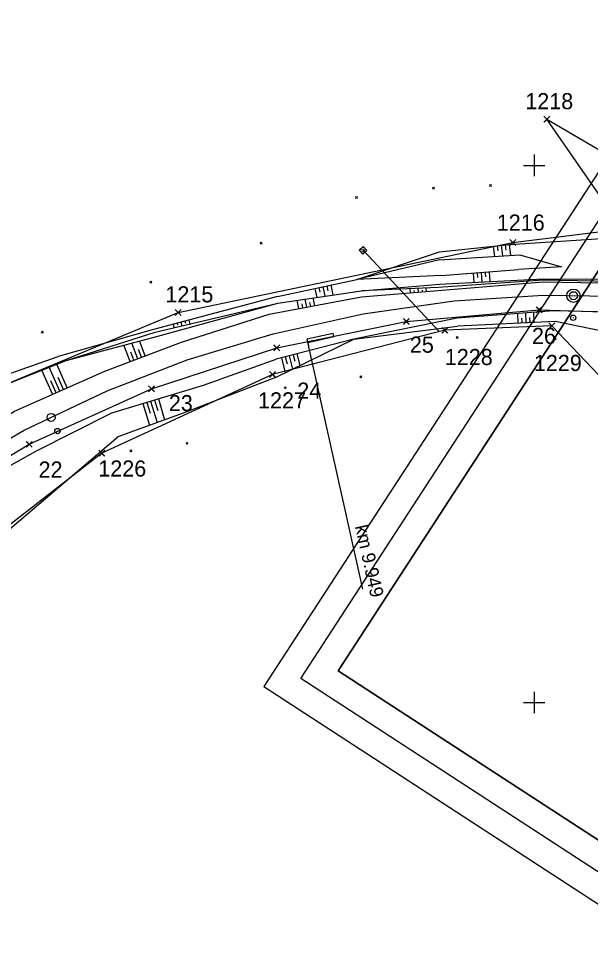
# Model space of a CAD drawing. Extents: x -866402 to -860377, y -1041908 to -1038598.
# Drawn here: x -862396.1 to -862289.5, y -1039343.6 to -1039172.6 of the extents above; entities that cross this region are included whole.
import ezdxf

# ---------------------------------------------------------------- set-up
doc = ezdxf.new("R2010")
doc.units = 0
for name, color, linetype in [('PS 01 trasa', 7, 'Continuous'), ('PS 02 trasa', 7, 'Continuous'), ('SO 01 trasa', 7, 'Continuous'), ('SZDC', 7, 'Continuous'), ('Vrstva 1', 7, 'Continuous'), ('Vrstva 25', 7, 'Continuous'), ('Vrstva 36', 7, 'Continuous'), ('Vrstva 48', 7, 'Continuous'), ('Vrstva 49', 7, 'Continuous'), ('Vrstva 5', 7, 'Continuous'), ('Vrstva 60', 7, 'Continuous'), ('Vrstva 7', 7, 'Continuous'), ('Vrstva 9', 7, 'Continuous')]:
    doc.layers.add(name, color=color, linetype=linetype)

msp = doc.modelspace()

# ---------------------------------------------------------------- linework, layer by layer
at = {"layer": 'PS 01 trasa'}
for points in [[(-862394.03, -1039251.93), (-862371.24, -1039241.59), (-862347.95, -1039233.96), (-862323.82, -1039229.06), (-862299.09, -1039226.88)], [(-862299.09, -1039226.88), (-862273.29, -1039227.68), (-862248.85, -1039231.2), (-862224.66, -1039236.92), (-862200.64, -1039243.69), (-862176.76, -1039250.51), (-862152.59, -1039257.52), (-862128.57, -1039264.44), (-862103.22, -1039271.85), (-862102.22, -1039272.14), (-862096.54, -1039273.77), (-862095.01, -1039274.21), (-862087.95, -1039276.24), (-862082.39, -1039277.83)], [(-862500.95, -1039382.24), (-862490.8, -1039355.08), (-862481.41, -1039336.58), (-862468.07, -1039315.92), (-862454.02, -1039298.95), (-862434.76, -1039279.82), (-862415.25, -1039264.75), (-862394.03, -1039251.93)]]:
    msp.add_lwpolyline(points, dxfattribs=at)
at = {"layer": 'PS 02 trasa'}
msp.add_lwpolyline([(-862490.8, -1039355.08), (-862481.41, -1039336.58), (-862468.07, -1039315.92), (-862454.02, -1039298.95), (-862434.76, -1039279.82), (-862415.25, -1039264.75), (-862394.03, -1039251.93), (-862371.24, -1039241.59), (-862347.95, -1039233.96), (-862323.82, -1039229.06), (-862299.09, -1039226.88), (-862273.29, -1039227.68), (-862248.85, -1039231.2), (-862224.66, -1039236.92), (-862200.64, -1039243.69)], dxfattribs=at)
at = {"layer": 'SO 01 trasa'}
for points in [[(-862394.03, -1039251.93), (-862371.24, -1039241.59), (-862347.95, -1039233.96), (-862323.82, -1039229.06), (-862299.09, -1039226.88)], [(-862299.09, -1039226.88), (-862273.29, -1039227.68), (-862248.85, -1039231.2), (-862224.66, -1039236.92), (-862200.64, -1039243.69), (-862176.76, -1039250.51), (-862152.59, -1039257.52), (-862128.57, -1039264.44), (-862103.22, -1039271.85)], [(-862500.95, -1039382.24), (-862490.8, -1039355.08), (-862481.41, -1039336.58), (-862468.07, -1039315.92), (-862454.02, -1039298.95), (-862434.76, -1039279.82), (-862415.25, -1039264.75), (-862394.03, -1039251.93)]]:
    msp.add_lwpolyline(points, dxfattribs=at)
at = {"layer": 'SZDC'}
for points in [[(-862521.71, -1039358.08), (-862507.17, -1039329.53), (-862500.14, -1039305.05), (-862498.55, -1039302.13), (-862487.25, -1039304.3), (-862484.62, -1039297.79), (-862467.38, -1039281.45), (-862436.33, -1039256.55), (-862366.3, -1039227.38), (-862303.99, -1039214.35), (-862283.48, -1039211.79), (-862297.66, -1039191.42), (-862263.73, -1039211.26), (-862253.31, -1039214.94), (-862234.51, -1039218.03), (-862199.37, -1039224.74)], [(-862296.71, -1039229.87), (-862316.65, -1039230.71), (-862348.72, -1039238.93), (-862380.51, -1039253.6), (-862410.85, -1039277.18), (-862440.53, -1039308.72), (-862448.04, -1039316.67), (-862455.09, -1039324.01), (-862466.78, -1039329.47), (-862479.41, -1039335.38), (-862482.88, -1039349.12), (-862498.59, -1039394.48), (-862504.52, -1039414.78), (-862507.77, -1039442.09), (-862507.54, -1039446.34), (-862506.21, -1039471.12), (-862505.87, -1039481.53), (-862505.25, -1039500.36), (-862503.67, -1039530.11), (-862504.26, -1039560.51), (-862512.94, -1039597.44), (-862522.21, -1039619.87), (-862533.82, -1039639.47), (-862574.41, -1039691.56)], [(-862268.74, -1039234), (-862264.19, -1039247.49), (-862269.23, -1039257.19), (-862284.23, -1039242.97), (-862296.71, -1039229.87)]]:
    msp.add_lwpolyline(points, dxfattribs=at)
at = {"layer": 'Vrstva 1'}
for points in [[(-862350.36, -1039297.02), (-861294.1, -1039983.97), (-861132.18, -1039735), (-862188.44, -1039048.05)], [(-862186.98, -1039054.97), (-861139.1, -1039736.46), (-861295.57, -1039977.05), (-862343.44, -1039295.55)], [(-862336.53, -1039294.09), (-861468.88, -1039858.37), (-861317.86, -1039626.16), (-862185.51, -1039061.88)], [(-862185.51, -1039061.88), (-861317.86, -1039626.16), (-861468.88, -1039858.37), (-862336.53, -1039294.09)]]:
    msp.add_lwpolyline(points, close=True, dxfattribs=at)
msp.add_lwpolyline([(-862494.61, -1039356.98), (-862487.83, -1039342.57), (-862479.6, -1039328.11), (-862470.61, -1039314.75), (-862460.78, -1039302.18), (-862456.07, -1039296.77), (-862449.22, -1039289.53), (-862437.48, -1039278.49), (-862424.62, -1039268.05), (-862410.54, -1039258.33), (-862394.98, -1039249.32), (-862379.54, -1039241.95), (-862364.62, -1039236.19), (-862348.59, -1039231.34), (-862331.87, -1039227.62), (-862314.89, -1039225.23), (-862298.26, -1039224.19), (-862281.07, -1039224.42), (-862264.02, -1039225.97), (-862246.91, -1039228.79), (-862230.83, -1039232.57), (-862214.22, -1039237.15), (-862198.47, -1039241.66)], dxfattribs=at)
at = {"layer": 'Vrstva 25'}
msp.add_line((-862317.68, -1039230.95), (-862331.88, -1039215.82), dxfattribs=at)
at = {"layer": 'Vrstva 36'}
for p, q in [((-862331.64, -1039215.35), (-862332.09, -1039215.33)), ((-862331.25, -1039215.76), (-862332.5, -1039215.72)), ((-862331.5, -1039216.15), (-862332.28, -1039216.13))]:
    msp.add_line(p, q, dxfattribs=at)
msp.add_lwpolyline([(-862331.9, -1039216.53), (-862332.58, -1039215.8), (-862331.86, -1039215.11), (-862331.17, -1039215.84), (-862331.9, -1039216.53)], dxfattribs=at)
at = {"layer": 'Vrstva 48'}
for p, q in [((-862307.63, -1039215.04), (-862307.42, -1039216.96)), ((-862306.88, -1039214.96), (-862306.78, -1039215.94)), ((-862306.14, -1039214.88), (-862305.93, -1039216.87)), ((-862305.39, -1039214.8), (-862305.28, -1039215.81)), ((-862304.65, -1039214.72), (-862304.43, -1039216.78)), ((-862311.37, -1039220.05), (-862311.24, -1039221.8)), ((-862310.63, -1039220), (-862310.56, -1039220.88)), ((-862309.88, -1039219.94), (-862309.74, -1039221.72)), ((-862309.13, -1039219.88), (-862309.06, -1039220.78)), ((-862308.38, -1039219.82), (-862308.24, -1039221.64)), ((-862338.64, -1039222.42), (-862338.44, -1039223.34)), ((-862337.9, -1039222.27), (-862337.5, -1039224.14)), ((-862340.84, -1039222.9), (-862340.48, -1039224.58)), ((-862340.1, -1039222.74), (-862339.92, -1039223.61)), ((-862339.37, -1039222.58), (-862338.99, -1039224.36)), ((-862323.04, -1039223.74), (-862323.1, -1039222.97)), ((-862322.3, -1039223.68), (-862322.33, -1039223.31)), ((-862321.55, -1039223.61), (-862321.6, -1039222.91)), ((-862320.8, -1039223.55), (-862320.83, -1039223.22)), ((-862320.05, -1039223.49), (-862320.1, -1039222.85)), ((-862343.83, -1039226.66), (-862344.12, -1039225.12)), ((-862343.1, -1039226.52), (-862343.24, -1039225.77)), ((-862342.36, -1039226.39), (-862342.64, -1039224.9)), ((-862341.62, -1039226.25), (-862341.76, -1039225.52)), ((-862340.88, -1039226.11), (-862341.15, -1039224.68)), ((-862302.99, -1039229.37), (-862303.08, -1039227.59)), ((-862301.49, -1039229.3), (-862301.58, -1039227.48)), ((-862299.99, -1039229.22), (-862300.08, -1039227.36)), ((-862365.79, -1039229.19), (-862365.6, -1039229.9)), ((-862365.07, -1039228.99), (-862364.97, -1039229.36)), ((-862364.34, -1039228.8), (-862364.14, -1039229.55)), ((-862302.24, -1039229.33), (-862302.29, -1039228.44)), ((-862300.74, -1039229.26), (-862300.79, -1039228.34)), ((-862367.24, -1039229.57), (-862367.06, -1039230.24)), ((-862366.52, -1039229.38), (-862366.43, -1039229.73)), ((-862372.44, -1039235.47), (-862373.48, -1039232.69)), ((-862375.24, -1039236.53), (-862376.4, -1039233.47)), ((-862373.84, -1039236), (-862374.94, -1039233.08)), ((-862373.14, -1039235.73), (-862373.68, -1039234.31)), ((-862374.54, -1039236.26), (-862375.11, -1039234.77)), ((-862347.09, -1039235.82), (-862346.38, -1039238.61)), ((-862346.36, -1039235.63), (-862346.03, -1039236.95)), ((-862345.64, -1039235.45), (-862345, -1039237.94)), ((-862344.91, -1039235.26), (-862344.61, -1039236.43)), ((-862344.18, -1039235.07), (-862343.62, -1039237.26)), ((-862388.34, -1039242.01), (-862390.3, -1039237.59)), ((-862386.97, -1039241.4), (-862388.9, -1039237.04)), ((-862389.71, -1039242.62), (-862391.69, -1039238.14)), ((-862387.65, -1039241.71), (-862388.62, -1039239.51)), ((-862389.02, -1039242.32), (-862390.01, -1039240.09)), ((-862372.86, -1039244.33), (-862371.64, -1039248.4)), ((-862372.14, -1039244.12), (-862371.54, -1039246.13)), ((-862371.43, -1039243.9), (-862370.23, -1039247.88)), ((-862370.71, -1039243.69), (-862370.11, -1039245.66)), ((-862369.99, -1039243.47), (-862368.82, -1039247.37))]:
    msp.add_line(p, q, dxfattribs=at)
at = {"layer": 'Vrstva 49'}
for p, q in [((-862308.31, -1039203.58), (-862307.95, -1039203.93)), ((-862308.31, -1039203.93), (-862307.95, -1039203.58)), ((-862318.92, -1039204.06), (-862318.57, -1039204.42)), ((-862318.92, -1039204.42), (-862318.57, -1039204.06)), ((-862333.26, -1039205.82), (-862332.9, -1039206.18)), ((-862333.26, -1039206.18), (-862332.9, -1039205.82)), ((-862304.63, -1039214.72), (-862261.74, -1039211.91)), ((-862351.01, -1039214.33), (-862350.66, -1039214.68)), ((-862351.01, -1039214.68), (-862350.66, -1039214.33)), ((-862317.64, -1039216.12), (-862304.63, -1039214.72)), ((-862333.02, -1039221.22), (-862317.64, -1039216.12)), ((-862317.63, -1039217.58), (-862302.71, -1039216.67)), ((-862302.71, -1039216.67), (-862294.91, -1039218.91)), ((-862317.63, -1039217.58), (-862333.02, -1039221.22)), ((-862294.91, -1039218.91), (-862302.9, -1039219.41)), ((-862317.35, -1039220.51), (-862333.02, -1039221.22)), ((-862317.35, -1039220.51), (-862302.9, -1039219.41)), ((-862371.57, -1039221.58), (-862371.22, -1039221.94)), ((-862371.57, -1039221.94), (-862371.22, -1039221.58)), ((-862347.82, -1039224.39), (-862333.02, -1039221.22)), ((-862332.14, -1039223.35), (-862317.66, -1039222.14)), ((-862317.66, -1039222.14), (-862298.34, -1039221.11)), ((-862298.34, -1039221.11), (-862281.02, -1039221.22)), ((-862280.97, -1039221.69), (-862298.32, -1039221.4)), ((-862347.76, -1039225.66), (-862332.14, -1039223.35)), ((-862370.1, -1039231.79), (-862347.76, -1039225.66)), ((-862349.33, -1039227.68), (-862332.14, -1039224.48)), ((-862296.42, -1039227.08), (-862314.38, -1039228.47)), ((-862281.28, -1039227.44), (-862296.42, -1039227.08)), ((-862314.38, -1039228.47), (-862333.62, -1039232.37)), ((-862296.11, -1039229.04), (-862314.26, -1039229.92)), ((-862276.49, -1039233.14), (-862296.11, -1039229.04)), ((-862391.77, -1039230.88), (-862391.42, -1039231.23)), ((-862391.77, -1039231.23), (-862391.42, -1039230.88)), ((-862333.62, -1039232.37), (-862314.26, -1039229.92)), ((-862387.19, -1039236.36), (-862370.1, -1039231.79)), ((-862348.21, -1039239.51), (-862333.62, -1039232.37)), ((-862333.62, -1039232.37), (-862348.08, -1039236.07)), ((-862314.54, -1039231.84), (-862314.18, -1039232.19)), ((-862314.54, -1039232.19), (-862314.18, -1039231.84)), ((-862296.26, -1039232.11), (-862295.91, -1039232.46)), ((-862296.26, -1039232.46), (-862295.91, -1039232.11)), ((-862404.66, -1039241.21), (-862388.64, -1039235.59)), ((-862406.47, -1039244), (-862387.19, -1039236.36)), ((-862332.45, -1039239.19), (-862332.1, -1039239.54)), ((-862332.45, -1039239.54), (-862332.1, -1039239.19)), ((-862346.53, -1039241.21), (-862346.17, -1039241.56)), ((-862346.53, -1039241.56), (-862346.17, -1039241.21)), ((-862364.83, -1039251.57), (-862364.48, -1039251.92)), ((-862364.83, -1039251.92), (-862364.48, -1039251.57)), ((-862375.31, -1039252.98), (-862374.96, -1039253.34)), ((-862375.31, -1039253.34), (-862374.96, -1039252.98))]:
    msp.add_line(p, q, dxfattribs=at)
for points in [[(-862298.32, -1039221.4), (-862317.91, -1039222.76), (-862332.14, -1039223.35)], [(-862332.14, -1039224.48), (-862316.38, -1039223.19), (-862298.34, -1039221.67), (-862280.86, -1039222.01)], [(-862347.82, -1039224.39), (-862370.9, -1039230.55), (-862388.64, -1039235.59)], [(-862387.19, -1039236.36), (-862370.6, -1039231.08), (-862347.76, -1039225.66)], [(-862412.43, -1039255.53), (-862396.79, -1039245.75), (-862379.97, -1039238.31), (-862365.67, -1039232.92), (-862349.33, -1039227.68)], [(-862378.63, -1039246.07), (-862361.59, -1039240.95), (-862348.08, -1039236.07)], [(-862348.21, -1039239.51), (-862364.71, -1039245.88), (-862377.52, -1039250.52)], [(-862466.67, -1039318.21), (-862457.25, -1039304.73), (-862446.14, -1039292.01), (-862434.17, -1039280.93), (-862421.79, -1039271.2), (-862409.09, -1039262.25), (-862392.66, -1039253.17), (-862378.63, -1039246.07)], [(-862435.35, -1039300.72), (-862426.7, -1039292.31), (-862418.36, -1039285.27), (-862377.52, -1039250.52)]]:
    msp.add_lwpolyline(points, dxfattribs=at)
at = {"layer": 'Vrstva 5'}
for p, q in [((-862300, -1039198), (-862300, -1039202)), ((-862302, -1039200), (-862298, -1039200)), ((-862300, -1039298), (-862300, -1039302)), ((-862302, -1039300), (-862298, -1039300))]:
    msp.add_line(p, q, dxfattribs=at)
at = {"layer": 'Vrstva 60'}
for p, q in [((-862297.21, -1039191.87), (-862298.21, -1039190.87)), ((-862297.21, -1039190.97), (-862298.21, -1039191.97)), ((-862298.11, -1039191.87), (-862297.11, -1039190.87)), ((-862298.11, -1039190.97), (-862297.11, -1039191.97)), ((-862297.66, -1039191.42), (-862297.66, -1039191.42)), ((-862303.54, -1039214.8), (-862304.54, -1039213.8)), ((-862303.54, -1039213.9), (-862304.54, -1039214.9)), ((-862304.44, -1039214.8), (-862303.44, -1039213.8)), ((-862304.44, -1039213.9), (-862303.44, -1039214.9)), ((-862303.99, -1039214.35), (-862303.99, -1039214.35)), ((-862365.85, -1039227.83), (-862366.85, -1039226.83)), ((-862365.85, -1039226.93), (-862366.85, -1039227.93)), ((-862366.75, -1039227.83), (-862365.75, -1039226.83)), ((-862366.75, -1039226.93), (-862365.75, -1039227.93)), ((-862366.3, -1039227.38), (-862366.3, -1039227.38)), ((-862298.64, -1039227.33), (-862299.64, -1039226.33)), ((-862298.64, -1039226.43), (-862299.64, -1039227.43)), ((-862299.54, -1039227.33), (-862298.54, -1039226.33)), ((-862299.54, -1039226.43), (-862298.54, -1039227.43)), ((-862299.09, -1039226.88), (-862299.09, -1039226.88)), ((-862323.37, -1039229.51), (-862324.37, -1039228.51)), ((-862323.37, -1039228.61), (-862324.37, -1039229.61)), ((-862324.27, -1039229.51), (-862323.27, -1039228.51)), ((-862324.27, -1039228.61), (-862323.27, -1039229.61)), ((-862323.82, -1039229.06), (-862323.82, -1039229.06)), ((-862296.26, -1039230.32), (-862297.26, -1039229.32)), ((-862297.16, -1039230.32), (-862296.16, -1039229.32)), ((-862316.2, -1039231.16), (-862317.2, -1039230.16)), ((-862316.2, -1039230.26), (-862317.2, -1039231.26)), ((-862317.1, -1039231.16), (-862316.1, -1039230.16)), ((-862317.1, -1039230.26), (-862316.1, -1039231.26)), ((-862316.65, -1039230.71), (-862316.65, -1039230.71)), ((-862296.26, -1039229.42), (-862297.26, -1039230.42)), ((-862297.16, -1039229.42), (-862296.16, -1039230.42)), ((-862296.71, -1039229.87), (-862296.71, -1039229.87)), ((-862347.5, -1039234.41), (-862348.5, -1039233.41)), ((-862347.5, -1039233.51), (-862348.5, -1039234.51)), ((-862348.4, -1039234.41), (-862347.4, -1039233.41)), ((-862348.4, -1039233.51), (-862347.4, -1039234.51)), ((-862347.95, -1039233.96), (-862347.95, -1039233.96)), ((-862348.27, -1039239.38), (-862349.27, -1039238.38)), ((-862348.27, -1039238.48), (-862349.27, -1039239.48)), ((-862349.17, -1039239.38), (-862348.17, -1039238.38)), ((-862349.17, -1039238.48), (-862348.17, -1039239.48)), ((-862348.72, -1039238.93), (-862348.72, -1039238.93)), ((-862370.8, -1039242.04), (-862371.8, -1039241.04)), ((-862370.8, -1039241.14), (-862371.8, -1039242.14)), ((-862371.7, -1039242.04), (-862370.7, -1039241.04)), ((-862371.7, -1039241.14), (-862370.7, -1039242.14)), ((-862371.24, -1039241.59), (-862371.24, -1039241.59)), ((-862393.58, -1039252.38), (-862394.58, -1039251.38)), ((-862393.58, -1039251.48), (-862394.58, -1039252.48)), ((-862394.48, -1039252.38), (-862393.48, -1039251.38)), ((-862394.48, -1039251.48), (-862393.48, -1039252.48)), ((-862394.03, -1039251.93), (-862394.03, -1039251.93)), ((-862380.06, -1039254.05), (-862381.06, -1039253.05)), ((-862380.06, -1039253.15), (-862381.06, -1039254.15)), ((-862380.96, -1039254.05), (-862379.96, -1039253.05)), ((-862380.96, -1039253.15), (-862379.96, -1039254.15)), ((-862380.51, -1039253.6), (-862380.51, -1039253.6))]:
    msp.add_line(p, q, dxfattribs=at)
at = {"layer": 'Vrstva 7'}
for p, q in [((-862292.7, -1039228.38), (-862292.8, -1039228.38)), ((-862388.83, -1039249.47), (-862388.73, -1039249.47))]:
    msp.add_line(p, q, dxfattribs=at)
for centre, radius in [((-862292.7, -1039224.27), 1.25), ((-862292.7, -1039224.27), 0.752), ((-862292.75, -1039228.38), 0.5), ((-862389.96, -1039246.93), 0.75), ((-862388.78, -1039249.47), 0.5)]:
    msp.add_circle(centre, radius, dxfattribs=at)
at = {"layer": 'Vrstva 9'}
for p, q in [((-862337.44, -1039231.29), (-862342.32, -1039232.38)), ((-862342.32, -1039232.38), (-862342.19, -1039232.96)), ((-862342.26, -1039232.67), (-862332, -1039278.87)), ((-862342.19, -1039232.96), (-862337.31, -1039231.88)), ((-862337.31, -1039231.88), (-862337.44, -1039231.29)), ((-862342.19, -1039232.96), (-862342.06, -1039233.55))]:
    msp.add_line(p, q, dxfattribs=at)

# ---------------------------------------------------------------- texts
at = {"layer": 'Vrstva 60'}
for s, p in [('1218', (-862301.67, -1039189.55)), ('1216', (-862306.97, -1039212.15)), ('1215', (-862368.68, -1039225.51)), ('26', (-862300.42, -1039233.25)), ('25', (-862323.16, -1039234.88)), ('1228', (-862316.65, -1039237.18)), ('1229', (-862300.07, -1039238.29)), ('24', (-862344.13, -1039243.44)), ('23', (-862368.04, -1039245.76)), ('1227', (-862351.43, -1039245.25)), ('1226', (-862381.18, -1039257.94)), ('22', (-862392.3, -1039258.14))]:
    msp.add_text(s, height=3, dxfattribs=at).set_placement(p)
at = {"layer": 'Vrstva 9'}
msp.add_text('km 9.949', height=2.5, rotation=282.5194, dxfattribs=at).set_placement((-862333.39, -1039267.2))

doc.saveas('drawing.dxf')
